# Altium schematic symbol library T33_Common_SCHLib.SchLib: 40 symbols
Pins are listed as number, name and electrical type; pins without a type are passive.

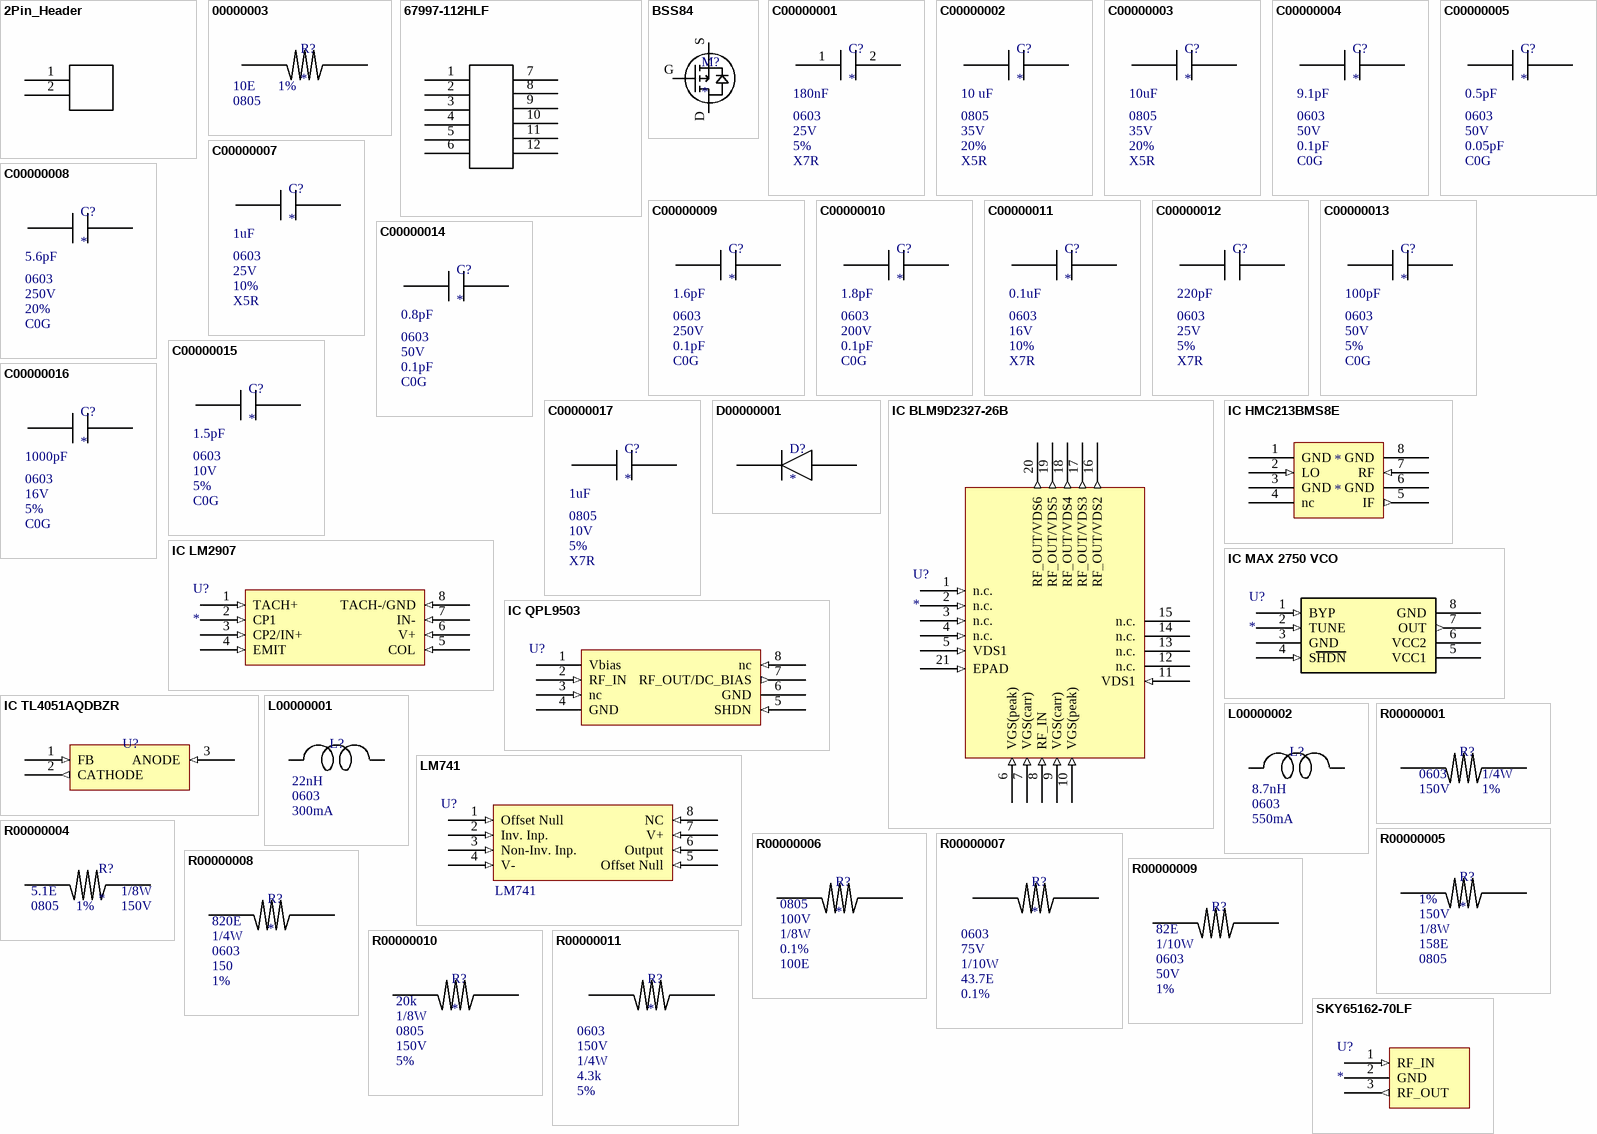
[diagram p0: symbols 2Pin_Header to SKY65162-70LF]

## 2Pin_Header
designator P?
footprint 2Pin_Header (2Pin)
pins: 1, 2

## 00000003
designator R?  Tolerance: 1%  Package: 0805  Resistance: 10E
RES CHIP 10E 0805 1%
pins: 1, 2

## 67997-112HLF
designator *
footprint Model Name (Footprint not found)
pins: 1, 2, 3, 4, 5, 6, 7, 8, 9, 10, 11, 12

## BSS84
designator M?
MOSFET P-CH DMOS 50V 130MA
pins: D, G, S

## C00000001
designator C?  Capacitance: 180nF  Voltage: 25V  Package: 0603  Tolerance: 5%  Dielectric: X7R
MLCC 180nF 25V X7R 0603
pins: 1, 2

## C00000002
designator C?  Dielectric: X5R  Tolerance: 20%  Voltage: 35V  Package: 0805  Capacitance: 10 uF
MLCC 10 uF 35V X5R 2012
pins: 1, 2

## C00000003
designator C?  Dielectric: X5R  Tolerance: 20%  Voltage: 35V  Package: 0805  Capacitance: 10uF
MLCC 10uF 35V X5R 0803
pins: 1, 2

## C00000004
designator C?  Dielectric: C0G  Tolerance: 0.1pF  Voltage: 50V  Package: 0603  Capacitance: 9.1pF
MLCC 9.1pF 50V 0603 C0G
pins: 1, 2

## C00000005
designator C?  Dielectric: C0G  Tolerance: 0.05pF  Voltage: 50V  Package: 0603  Capacitance: 0.5pF
MLCC 0.5pF 50V 0603 C0G
pins: 1, 2

## C00000007
designator C?  Dielectric: X5R  Tolerance: 10%  Voltage: 25V  Package: 0603  Capacitance: 1uF
MLCC 1uF 25V X5R 0603
pins: 1, 2

## C00000008
designator C?  Dielectric: C0G  Tolerance: 20%  Voltage: 250V  Package: 0603  Capacitance: 5.6pF
MLCC 5.6pF 250V C0G 0603
pins: 1, 2

## C00000009
designator C?  Dielectric: C0G  Tolerance: 0.1pF  Voltage: 250V  Package: 0603  Capacitance: 1.6pF
MLCC 1.6 pF 250V C0G 0603
pins: 1, 2

## C00000010
designator C?  Dielectric: C0G  Tolerance: 0.1pF  Voltage: 200V  Package: 0603  Capacitance: 1.8pF
MLCC 1.8 pF 250V C0G 0603
pins: 1, 2

## C00000011
designator C?  Dielectric: X7R  Tolerance: 10%  Voltage: 16V  Package: 0603  Capacitance: 0.1uF
MLCC 0.1uF 16V 0603 X7R
pins: 1, 2

## C00000012
designator C?  Dielectric: X7R  Tolerance: 5%  Voltage: 25V  Package: 0603  Capacitance: 220pF  (hidden comment: *)
MLCC 220pF 5% 25V 0603 X7R
pins: 1, 2

## C00000013
designator C?  Dielectric: C0G  Tolerance: 5%  Voltage: 50V  Package: 0603  Capacitance: 100pF
MLCC 100pF 5% 50V 0603
pins: 1, 2

## C00000014
designator C?  Dielectric: C0G  Tolerance: 0.1pF  Voltage: 50V  Package: 0603  Capacitance: 0.8pF
Capacitors MLCC - SMD/SMT 50V 0.8pF C0G 0603 0.1pF
footprint ML03510R8BAT2A (MLCC - SMD/SMT 50V 0.8pF C0G 0603 0.1pF)
pins: 1, 2

## C00000015
designator C?  Dielectric: C0G  Tolerance: 5%  Voltage: 10V  Package: 0603  Capacitance: 1.5pF
MLCC - SMD/SMT 0603 1.5pF 10volts C0G +/-0.25p
footprint VJ0603A1R5CXQCW1BC (MLCC - SMD/SMT 0603 1.5pF 10volts C0G +/-0.25pF)
pins: 1, 2

## C00000016
designator C?  Dielectric: C0G  Tolerance: 5%  Voltage: 16V  Package: 0603  Capacitance: 1000pF
MLCC - SMD/SMT 16V 1000pF 0603 C0G 0.01
footprint C0603C102F4GACTU (MLCC - SMD/SMT 16V 1000pF 0603 C0G 0.01)
pins: 1, 2

## C00000017
designator C?  Dielectric: X7R  Tolerance: 5%  Voltage: 10V  Package: 0805  Capacitance: 1uF
MLCC - SMD/SMT 10V 1uF X7R 0805 10% / RoHS Compliant
footprint EMK212B7105KG-T (MLCC - SMD/SMT 0805 16VDC 1uF 10% X7R)
pins: 1, 2

## D00000001
designator D?
PIN DIODE .45 Pf .45 OHM .37 nH, 1-8GHz, SMP1334-084LF
pins: 1, 2

## IC BLM9D2327-26B
designator U?
LDMOS 2-stage integrated Doherty MMIC
footprint BLM9D2327-26B (LDMOS 2-stage integrated Doherty MMIC)
pins: 1 n.c. (in) "not connected", 2 n.c. (in) "not connected", 3 n.c. (in) "not connected", 4 n.c. (in) "not connected", 5 VDS1 (in) "drain-source voltage of driver stages", 6 VGS(peak) (in) "gate-source voltage of peaking", 7 VGS(carr) (in) "gate-source voltage of carrier", 8 RF_IN (in) "RF input", 9 VGS(carr) (in) "gate-source voltage of carrier", 10 VGS(peak) (in) "gate-source voltage of peaking", 11 VDS1 (in) "drain-source voltage of driver stages", 12 n.c. "not connected", 13 n.c. "not connected", 14 n.c. "not connected", 15 n.c. "not connected", 16 RF_OUT/VDS2 (out) "RF output / drain-source voltage of final stages", 17 RF_OUT/VDS3 (out) "RF output / drain-source voltage of final stages", 18 RF_OUT/VDS4 (out) "RF output / drain-source voltage of final stages", 19 RF_OUT/VDS5 (out) "RF output / drain-source voltage of final stages", 20 RF_OUT/VDS6 (out) "RF output / drain-source voltage of final stages", 21 EPAD (in) "Thermal Pad"

## IC HMC213BMS8E
designator *
pins: 1 GND (power), 2 LO (in), 3 GND (power), 4 nc, 5 IF (out), 6 GND (power), 7 RF (in), 8 GND (power)

## IC LM2907
designator U?
pins: 1 TACH+ (in), 2 CP1 (in), 3 CP2/IN+ (in), 4 EMIT (in), 5 COL (in), 6 V+ (in), 7 IN- (in), 8 TACH-/GND (in)

## IC MAX 2750 VCO
designator U?
2.4-2.5 GHz VCO
pins: 1 BYP (in), 2 TUNE (in), 3 GND (power), 4 SHDN (in), 5 VCC1 (power), 6 VCC2 (power), 7 OUT (out), 8 GND (power)

## IC QPL9503
designator U?  (value not drawn)
pins: 1 Vbias (power), 2 RF_IN (in), 3 nc (in), 4 GND (power), 5 SHDN (in), 6 GND (power), 7 RF_OUT/DC_BIAS (out), 8 nc (in)

## IC TL4051AQDBZR
designator U?  (value not drawn)
Precision voltage reference
pins: 1 FB (in) "Feedback", 2 CATHODE (out) "Cathode", 3 ANODE (in) "Anode"

## L00000001
designator L?  Inductance: 22nH  Package: 0603  Imax: 300mA  (hidden comment: *)
22nH 300mA 0603 RF Inductor
pins: 5, 5

## L00000002
designator L?  Inductance: 8.7nH  Package: 0603  Imax: 550mA  (hidden comment: *)
IND 8.7nH 550mA 0603
footprint LQW18AS8N7J00D (8.7nH 0603)
pins: 1, 2

## LM741
designator U?  PN: LM741  (hidden comment: *)
pins: 1 Offset Null (in), 2 Inv. Inp. (in) "Inverting Input", 3 Non-Inv. Inp. (in) "Non-Inverting Input", 4 V- (in), 5 Offset Null (in), 6 Output (in), 7 V+ (in), 8 NC (in)

## R00000001
designator R?  Tolerance: 1%  Package: 0603  Voltage Rating: 150V  Power: 1/4W  (hidden comment: *)
RES CHIP 866 0603 1%; Resistance: 866E
footprint 0603 (Footprint not found)
pins: 1, 2

## R00000004
designator R?  Voltage Rating: 150V  Tolerance: 1%  Package: 0805  Power: 1/8W  Resistance: 5.1E
RES CHIP 5.1E 0805 1%
pins: 1, 2

## R00000005
designator R?  Package: 0805  Voltage Rating: 150V  Power: 1/8W  Tolerance: 1%  Resistance: 158E
RES CHIP 158E 0805 1%
pins: 1, 2

## R00000006
designator R?  Resistance: 100E  Tolerance: 0.1%  Power: 1/8W  Voltage Rating: 100V  Package: 0805
RES CHIP 100E 0.1%
pins: 1, 2

## R00000007
designator R?  Tolerance: 0.1%  Resistance: 43.7E  Power: 1/10W  Voltage Rating: 75V  Package: 0603
RES CHIP 43.7E 0603 0.1%
pins: 1, 2

## R00000008
designator R?  Voltage Rating: 150  Tolerance: 1%  Package: 0603  Power: 1/4W  Resistance: 820E
RES CHIP 820E 1%
pins: 1, 2

## R00000009
designator R?  Voltage Rating: 50V  Tolerance: 1%  Package: 0603  Power: 1/10W  Resistance: 82E  (hidden comment: *)
RES CHIP 82E 5% 1/10W
pins: 1, 2

## R00000010
designator R?  Voltage Rating: 150V  Tolerance: 5%  Package: 0805  Power: 1/8W  Resistance: 20k
RES CHIP 20k 5% / CR0805-JW-203ELF
footprint CR0805-JW-203ELF (Thick Film Resistors - SMD 20K 5%)
pins: 1, 2

## R00000011
designator R?  Tolerance: 5%  Resistance: 4.3k  Power: 1/4W  Voltage Rating: 150V  Package: 0603
RES CHIP 4.3k 5% 0603 ESR03EZPJ432
footprint ESR03EZPJ432 (Thick FilmResistors - SMD 0603 4.3Kohm 5% Anti Surge AEC-Q200)
pins: 1, 2

## SKY65162-70LF
designator U?
SKY65162-70LF: 400 to 3800 MHz Linear Power Amplifier.; Gain: 13dB
footprint SKY65162-70LF (RF Amplifier 400-2700MHz NF 3.6dB Gain 24dB)
pins: 1 RF_IN (in) "RF Input", 2 GND (power), 3 RF_OUT (out) "Amplified Output"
